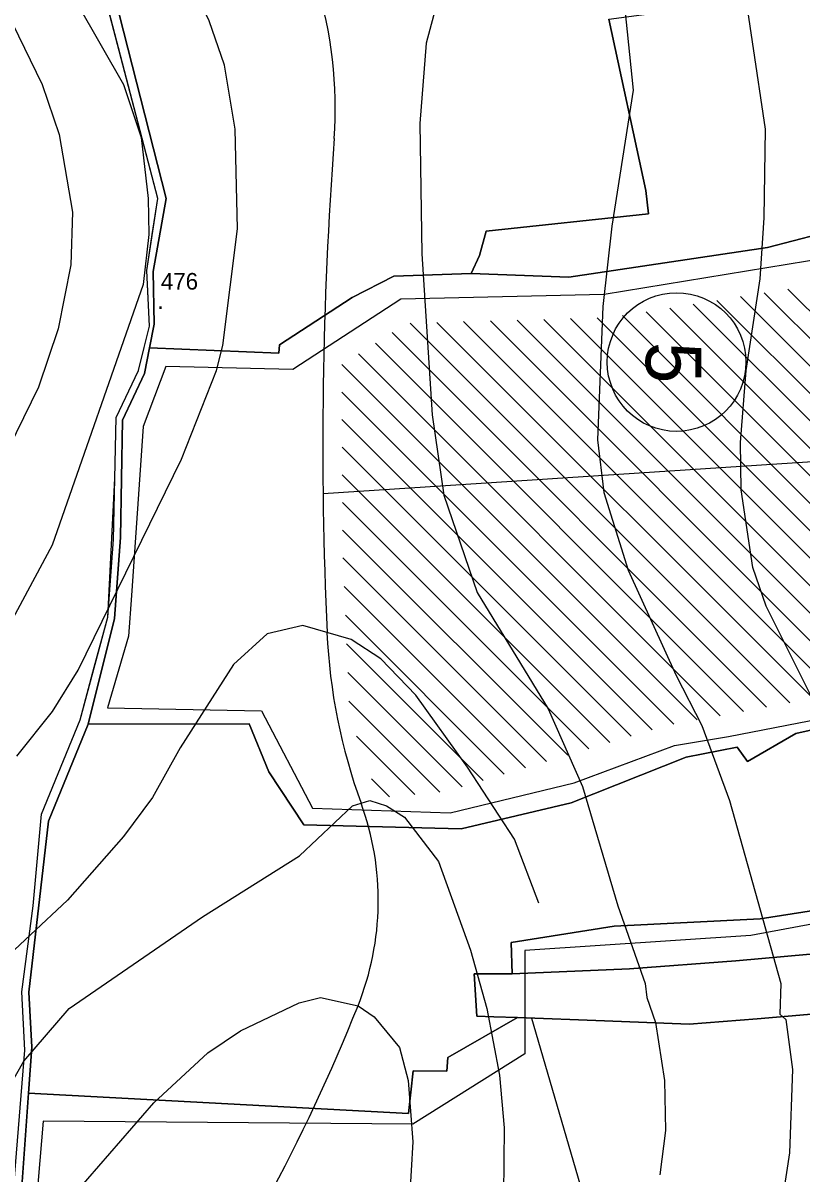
# Model space of a CAD drawing. Extents: x -510989 to -501240, y -1184665 to -1176089.
# Drawn here: x -510432.6 to -510151.7, y -1179085.6 to -1178670.8 of the extents above; entities that cross this region are included whole.
import ezdxf

# ---------------------------------------------------------------- set-up
doc = ezdxf.new("R2010")
doc.units = 0
for name, color, linetype in [('lesni_pozemek', 7, 'Continuous'), ('NAVRH_interakcni_prvky', 7, 'Continuous'), ('NAVRH_rozvodnice', 7, 'Continuous'), ('orna_puda', 7, 'Continuous'), ('ostatni_plocha_x_ostatni_komunikace', 7, 'Continuous'), ('popis', 7, 'Continuous'), ('STAV_erozne_ohrozene_plochy', 7, 'Continuous'), ('STAV_odtokove_linie', 7, 'Continuous'), ('STAV_povodi', 7, 'Continuous'), ('STAV_systematicke_odvodneni', 7, 'Continuous'), ('trvaly_travni_porost', 7, 'Continuous'), ('vrstevnice_01', 7, 'Continuous'), ('vrstevnice_02', 7, 'Continuous'), ('vrstevnice_03', 7, 'Continuous'), ('vrstevnice_05', 7, 'Continuous')]:
    doc.layers.add(name, color=color, linetype=linetype)

msp = doc.modelspace()

# ---------------------------------------------------------------- linework, layer by layer
at = {"layer": 'lesni_pozemek'}
for points in [[(-510221.43, -1178669.35), (-510208.07, -1178731.15), (-510207.11, -1178739.59), (-510265.59, -1178745.79), (-510267.96, -1178754.6), (-510271, -1178761.12), (-510298.87, -1178762.03), (-510313.94, -1178769.77), (-510340.15, -1178786.75), (-510340.38, -1178789.73), (-510386.97, -1178787.83), (-510385.28, -1178779.31), (-510385.72, -1178760.29), (-510381.04, -1178734.06), (-510420.88, -1178577.47)], [(-510111.43, -1178985.02), (-510166.83, -1178993.63), (-510219.48, -1178996.35), (-510256.55, -1179002.25), (-510256.19, -1179013.55), (-510263.58, -1179013.51), (-510269.95, -1179013.47), (-510269.01, -1179028.74), (-510262.8, -1179028.97), (-510254.34, -1179029.28), (-510279.43, -1179043.62), (-510279.78, -1179048.59), (-510291.92, -1179048.45), (-510293.61, -1179063.89), (-510430.62, -1179056.54), (-510429.46, -1179039.96), (-510430.57, -1179020.06), (-510423.37, -1178958.53), (-510409.14, -1178923.55), (-510351.05, -1178923.37), (-510344.01, -1178940.67), (-510331.36, -1178959.82), (-510274.65, -1178961.21), (-510234.91, -1178951.87), (-510193.46, -1178935.36), (-510175.09, -1178931.75), (-510171.37, -1178936.98), (-510153.99, -1178926.88), (-510103.65, -1178915.7)]]:
    msp.add_lwpolyline(points, dxfattribs=at)
msp.add_lwpolyline([(-510127.13, -1178656.8), (-510124.74, -1178689.41), (-510122.29, -1178707.36), (-510117.58, -1178726.68), (-510112.7, -1178734.99), (-510110.66, -1178742.05), (-510145.7, -1178746.86), (-510164.15, -1178751.65), (-510235.82, -1178762.37), (-510271, -1178761.12), (-510267.96, -1178754.6), (-510265.59, -1178745.79), (-510207.11, -1178739.59), (-510208.07, -1178731.15), (-510221.43, -1178669.35)], close=True, dxfattribs=at)
at = {"layer": 'NAVRH_interakcni_prvky'}
msp.add_line((-510249.3, -1179029.48), (-510221.53, -1179124.34), dxfattribs=at)
at = {"layer": 'NAVRH_rozvodnice'}
for centre, radius, start, end in [((-510470.68, -1178701.35), 150.67, 355.7868, 17.5161), ((-508815.72, -1178823.26), 1508.78, 175.78679, 182.55411), ((-510117.14, -1178881.32), 206.07, 182.5541, 200.0604), ((-510406.69, -1178987.05), 102.18, 338.1981, 20.0604), ((-510932.56, -1178776.7), 668.57, 324.80829, 338.19812)]:
    msp.add_arc(centre, radius, start, end, dxfattribs=at)
at = {"layer": 'orna_puda'}
msp.add_lwpolyline([(-510103.65, -1178915.7), (-510153.99, -1178926.88), (-510171.37, -1178936.98), (-510175.09, -1178931.75), (-510193.46, -1178935.36), (-510234.91, -1178951.87), (-510274.65, -1178961.21), (-510331.36, -1178959.82), (-510344.01, -1178940.67), (-510351.05, -1178923.37), (-510409.14, -1178923.55), (-510399.61, -1178885.48), (-510397.46, -1178856.26), (-510396.72, -1178813.98), (-510388.81, -1178797.11), (-510386.97, -1178787.83), (-510340.38, -1178789.73), (-510340.15, -1178786.75), (-510313.94, -1178769.77), (-510298.87, -1178762.03), (-510271, -1178761.12), (-510235.82, -1178762.37), (-510164.15, -1178751.65), (-510145.7, -1178746.86)], dxfattribs=at)
for points in [[(-510111.43, -1178985.02), (-510069.04, -1178975.19), (-510065.18, -1178994.04), (-510121.92, -1179004.03), (-510175.61, -1179008.78), (-510213.93, -1179011.69), (-510256.19, -1179013.55), (-510256.55, -1179002.25), (-510219.48, -1178996.35), (-510166.83, -1178993.63)], [(-510065.18, -1178994.04), (-510019.96, -1178985.63), (-510016.4, -1179000.41), (-510034.21, -1179006.39), (-510037.15, -1179006.7), (-510109.19, -1179024.7), (-510167.87, -1179029.73), (-510192.45, -1179031.68), (-510222.9, -1179030.42), (-510254.34, -1179029.28), (-510262.8, -1179028.97), (-510269.01, -1179028.74), (-510269.95, -1179013.47), (-510263.58, -1179013.51), (-510256.19, -1179013.55), (-510213.93, -1179011.69), (-510175.61, -1179008.78), (-510121.92, -1179004.03)]]:
    msp.add_lwpolyline(points, close=True, dxfattribs=at)
at = {"layer": 'ostatni_plocha_x_ostatni_komunikace'}
for points in [[(-510523.48, -1177921.32), (-510513.02, -1178041.26), (-510501.95, -1178090.1), (-510478.78, -1178124.83), (-510474.81, -1178130.78), (-510425.86, -1178204.15), (-510402.34, -1178335.6), (-510408.67, -1178405.28), (-510421.14, -1178466.58), (-510420.88, -1178577.47), (-510381.04, -1178734.06), (-510385.72, -1178760.29), (-510385.28, -1178779.31), (-510386.97, -1178787.83), (-510388.81, -1178797.11), (-510396.72, -1178813.98), (-510397.46, -1178856.26), (-510399.61, -1178885.48), (-510409.14, -1178923.55), (-510423.37, -1178958.53), (-510430.57, -1179020.06), (-510429.46, -1179039.96), (-510430.62, -1179056.54), (-510433.11, -1179091.84)], [(-510441, -1179151), (-510432, -1179041), (-510433, -1179020), (-510429, -1178989), (-510426, -1178956), (-510412, -1178922), (-510407, -1178903), (-510402, -1178885), (-510400, -1178857), (-510399, -1178813), (-510391, -1178796), (-510388.94, -1178787.75), (-510387, -1178780), (-510388, -1178760), (-510384, -1178734), (-510425, -1178577), (-510425, -1178466), (-510413, -1178406), (-510407, -1178337), (-510431, -1178203), (-510507, -1178091), (-510517, -1178037), (-510522, -1177979), (-510527, -1177923)]]:
    msp.add_lwpolyline(points, dxfattribs=at)
at = {"layer": 'popis'}
msp.add_lwpolyline([(-510441, -1179151), (-510432, -1179041), (-510433, -1179020), (-510429, -1178989), (-510426, -1178956), (-510412, -1178922), (-510402, -1178885), (-510399.5, -1178835), (-510399, -1178813), (-510391, -1178796), (-510388.94, -1178787.75), (-510387, -1178780), (-510387.5, -1178770), (-510388, -1178760), (-510386, -1178747), (-510384, -1178734), (-510404.5, -1178655.5), (-510425, -1178577), (-510425, -1178521.5), (-510425, -1178466), (-510413, -1178406), (-510410, -1178371.5), (-510407, -1178337), (-510419, -1178270)], dxfattribs=at)
at = {"layer": 'STAV_erozne_ohrozene_plochy'}
for p, q in [((-510165.32, -1178768.04), (-510042.71, -1178890.64)), ((-510156.79, -1178766.67), (-510070.16, -1178853.29)), ((-510190.91, -1178772.15), (-510066.35, -1178896.7)), ((-510182.38, -1178770.78), (-510058.47, -1178894.68)), ((-510173.85, -1178769.41), (-510050.59, -1178892.66)), ((-510225.56, -1178777.09), (-510097.87, -1178904.79)), ((-510216.49, -1178776.26), (-510089.99, -1178902.77)), ((-510207.96, -1178774.89), (-510082.11, -1178900.74)), ((-510199.44, -1178773.52), (-510074.23, -1178898.72)), ((-510293.01, -1178778.94), (-510156.11, -1178915.84)), ((-510283.37, -1178778.68), (-510147.75, -1178914.3)), ((-510273.74, -1178778.41), (-510139.39, -1178912.76)), ((-510264.1, -1178778.15), (-510131.03, -1178911.22)), ((-510254.47, -1178777.88), (-510122.67, -1178909.68)), ((-510244.83, -1178777.62), (-510114.32, -1178908.14)), ((-510235.2, -1178777.35), (-510105.96, -1178906.6)), ((-510299.46, -1178782.39), (-510164.47, -1178917.38)), ((-510305.54, -1178786.21), (-510172.83, -1178918.92)), ((-510317.71, -1178793.83), (-510189.54, -1178922)), ((-510311.63, -1178790.02), (-510181.18, -1178920.46)), ((-510317.65, -1178803.79), (-510197.9, -1178923.55)), ((-510317.6, -1178813.75), (-510205.74, -1178925.61)), ((-510317.54, -1178823.71), (-510213.36, -1178927.89)), ((-510317.48, -1178833.67), (-510220.98, -1178930.17)), ((-510317.42, -1178843.63), (-510228.59, -1178932.45)), ((-510317.36, -1178853.58), (-510236.21, -1178934.73)), ((-510317.24, -1178863.61), (-510243.83, -1178937.01)), ((-510316.81, -1178873.93), (-510251.45, -1178939.29)), ((-510316.39, -1178884.25), (-510259.07, -1178941.57)), ((-510315.97, -1178894.57), (-510266.69, -1178943.86)), ((-510315.55, -1178904.89), (-510274.31, -1178946.14)), ((-510315.13, -1178915.21), (-510282.37, -1178947.97)), ((-510312.38, -1178927.86), (-510291.39, -1178948.85)), ((-510306.9, -1178943.24), (-510300.42, -1178949.72))]:
    msp.add_line(p, q, dxfattribs=at)
at = {"layer": 'STAV_odtokove_linie'}
msp.add_line((-510324.4, -1178840.42), (-510070.91, -1178823.71), dxfattribs=at)
msp.add_circle((-510196.95, -1178792.98), 25, dxfattribs=at)
at = {"layer": 'STAV_povodi'}
for centre, radius, start, end in [((-510470.68, -1178701.35), 150.67, 355.7868, 17.5161), ((-508815.72, -1178823.26), 1508.78, 175.78679, 182.55411), ((-510117.14, -1178881.32), 206.07, 182.5541, 200.0604), ((-510406.69, -1178987.05), 102.18, 338.1981, 20.0604), ((-510932.56, -1178776.7), 668.57, 324.80829, 338.19812)]:
    msp.add_arc(centre, radius, start, end, dxfattribs=at)
at = {"layer": 'STAV_systematicke_odvodneni'}
for p, q in [((-510114.56, -1178750.84), (-510223.03, -1178768.65)), ((-510223.03, -1178768.65), (-510296.42, -1178770.27)), ((-510296.42, -1178770.27), (-510335.27, -1178795.65)), ((-510381.14, -1178794.57), (-510389.24, -1178816.16)), ((-510335.27, -1178795.65), (-510381.14, -1178794.57)), ((-510389.24, -1178816.16), (-510393.55, -1178877.17)), ((-510393.55, -1178877.17), (-510394.63, -1178891.75)), ((-510394.63, -1178891.75), (-510402.19, -1178917.66)), ((-510402.19, -1178917.66), (-510346.61, -1178918.74)), ((-510346.61, -1178918.74), (-510328.26, -1178953.83)), ((-510178.24, -1178927.92), (-510144.78, -1178921.44)), ((-510197.66, -1178931.16), (-510178.24, -1178927.92)), ((-510233.82, -1178944.65), (-510197.66, -1178931.16)), ((-510278.61, -1178955.45), (-510233.82, -1178944.65)), ((-510328.26, -1178953.83), (-510278.61, -1178955.45)), ((-510062.21, -1178979.21), (-510170.14, -1178999.72)), ((-510170.14, -1178999.72), (-510251.63, -1179005.12)), ((-510251.63, -1179005.12), (-510251.63, -1179042.37)), ((-510251.63, -1179042.37), (-510292.1, -1179067.74)), ((-510425.39, -1179066.66), (-510432.41, -1179152.5)), ((-510292.1, -1179067.74), (-510425.39, -1179066.66))]:
    msp.add_line(p, q, dxfattribs=at)
at = {"layer": 'trvaly_travni_porost'}
msp.add_lwpolyline([(-510433.11, -1179091.84), (-510430.62, -1179056.54), (-510293.61, -1179063.89), (-510291.92, -1179048.45), (-510279.78, -1179048.59), (-510279.43, -1179043.62), (-510254.34, -1179029.28), (-510222.9, -1179030.42), (-510192.45, -1179031.68), (-510167.87, -1179029.73), (-510109.19, -1179024.7), (-510109.02, -1179026.52), (-510071.2, -1179020.86), (-510029.46, -1179008.65), (-509927.85, -1178970.7), (-509917.46, -1178984.92), (-509903.17, -1179002.26), (-509870.94, -1179014.78), (-509855.48, -1179025.9), (-509837.62, -1179037.72), (-509822.01, -1179053.74), (-509808.93, -1179070.27), (-509783.93, -1179094.34)], dxfattribs=at)
at = {"layer": 'vrstevnice_01'}
for points in [[(-510434.81, -1178935), (-510422, -1178919), (-510412.69, -1178904), (-510375.41, -1178828), (-510362.81, -1178796), (-510360.59, -1178787), (-510355.31, -1178745), (-510356.09, -1178709), (-510359.91, -1178686), (-510365.5, -1178670), (-510375.81, -1178649), (-510393.41, -1178623), (-510430.19, -1178571), (-510436.59, -1178557)], [(-510124, -1179124), (-510117.31, -1179082), (-510115.31, -1179034), (-510116.69, -1179012), (-510124.41, -1178972), (-510143.59, -1178923), (-510164.69, -1178881), (-510169.41, -1178867), (-510173.69, -1178839), (-510173.91, -1178822), (-510171.81, -1178796), (-510166.81, -1178763), (-510165.31, -1178741), (-510164.91, -1178709), (-510174.31, -1178646), (-510173.59, -1178625)], [(-510274.41, -1178630), (-510287.19, -1178678), (-510289.5, -1178707), (-510288.81, -1178754), (-510285.09, -1178812), (-510280.91, -1178841), (-510268.91, -1178876), (-510243.31, -1178918), (-510230.91, -1178946), (-510218.19, -1178989), (-510208.31, -1179017), (-510207.69, -1179022), (-510204.59, -1179031), (-510201.31, -1179052), (-510201, -1179070), (-510203, -1179086)], [(-510436.41, -1178671), (-510425.69, -1178693), (-510419.59, -1178711), (-510414.81, -1178739), (-510415.41, -1178758), (-510419.91, -1178781), (-510427, -1178802), (-510443.31, -1178835)]]:
    msp.add_lwpolyline(points, dxfattribs=at)
at = {"layer": 'vrstevnice_02'}
for points in [[(-510450.09, -1178402), (-510451.31, -1178416), (-510462.69, -1178461), (-510468.41, -1178490), (-510472, -1178518), (-510471, -1178550), (-510466.09, -1178573), (-510457.81, -1178595), (-510446.19, -1178618), (-510413, -1178664), (-510396.41, -1178693), (-510390, -1178712), (-510387.5, -1178734), (-510387.19, -1178747), (-510389.31, -1178765), (-510422.09, -1178859), (-510449, -1178909), (-510466.5, -1178928), (-510486.81, -1178959), (-510494.31, -1178973), (-510511.31, -1179014), (-510514.09, -1179038), (-510524.81, -1179082), (-510535.31, -1179107)], [(-510219, -1178633), (-510212.59, -1178695), (-510220.31, -1178744), (-510223.5, -1178773), (-510225.41, -1178821), (-510223.19, -1178840), (-510214.41, -1178868), (-510197.09, -1178906), (-510187.81, -1178924), (-510177.81, -1178951), (-510159.31, -1179017), (-510159.69, -1179028), (-510157.59, -1179030), (-510155.19, -1179048), (-510156.19, -1179078), (-510161.91, -1179115)], [(-510464, -1179104), (-510445.59, -1179068), (-510432.31, -1179045), (-510416, -1179026), (-510367.91, -1178993), (-510332.91, -1178971), (-510313.81, -1178953), (-510307.59, -1178951), (-510301.59, -1178953), (-510295.09, -1178957), (-510282.81, -1178973), (-510271.31, -1179005), (-510265.31, -1179026), (-510260.81, -1179050), (-510259.09, -1179069), (-510259.41, -1179093)]]:
    msp.add_lwpolyline(points, dxfattribs=at)
at = {"layer": 'vrstevnice_03'}
for points in [[(-510246.59, -1178988), (-510255.41, -1178965), (-510272.31, -1178939), (-510291, -1178913), (-510303.59, -1178900), (-510314.31, -1178893), (-510331.69, -1178888), (-510344.59, -1178891), (-510356.69, -1178902), (-510375.91, -1178932), (-510385.91, -1178950), (-510396.41, -1178964), (-510416.59, -1178987), (-510443.41, -1179012), (-510455, -1179030), (-510462.59, -1179050)], [(-510504.59, -1179166), (-510490, -1179158), (-510465.69, -1179140), (-510440.91, -1179118), (-510413.19, -1179092), (-510385.41, -1179060), (-510366, -1179042), (-510354.19, -1179034), (-510333.09, -1179024), (-510325.31, -1179022), (-510311.81, -1179025), (-510306, -1179029), (-510296.81, -1179040), (-510293.69, -1179052), (-510292, -1179074), (-510293.91, -1179105), (-510296.59, -1179119), (-510307.81, -1179158), (-510313.59, -1179172), (-510320, -1179194), (-510322.09, -1179197), (-510327.19, -1179217), (-510332.09, -1179247)]]:
    msp.add_lwpolyline(points, dxfattribs=at)

# ---------------------------------------------------------------- texts
at = {"layer": 'STAV_odtokove_linie'}
msp.add_text('5', height=20, rotation=270, dxfattribs=at).set_placement((-510208.03, -1178785.77))
at = {"layer": 'vrstevnice_05'}
for s, p in [('476', (-510382.88, -1178766.88)), ('.', (-510384.16, -1178773.86))]:
    msp.add_text(s, height=6, dxfattribs=at).set_placement(p)

doc.saveas('drawing.dxf')
